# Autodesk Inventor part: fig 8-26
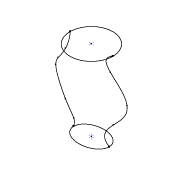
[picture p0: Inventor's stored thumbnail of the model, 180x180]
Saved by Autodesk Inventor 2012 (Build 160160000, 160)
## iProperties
Shininess: 64.0
Length Units: 11269
Angle Units: 11279
Time Units: 11290
Mass Units: 11283
Length Display Precision: 3
Angle Display Precision: 2
Compacted: True
Part Number: fig 8-26
Document SubType Name: Modeling
Created: 2002-12
Designer: deepak
Density: 1 g/cm^3
Material: Default
Density: 0.0
Volumn: 0.0
Area: 0.0
PropertySet Name: Model Information
Control State: 0
Master: False
Checked Out: False
Author: deepak
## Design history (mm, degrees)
sketch "Sketch1"
  geometry: 2 further points; 1 other entity
  constraints: 1 coincident, 3 other
workplane "Work Plane1"
workplane "Work Plane2"
sketch "Sketch3"
  geometry: C1 r 60 at (0, 0); 1 further point
  constraints: 1 centre point, 1 coincident, 1 other
sketch "Sketch4"
  geometry: 8 further points
  constraints: 8 other
sketch "Sketch5"
  geometry: 6 further points
  constraints: 6 other
sketch "Sketch6"
  geometry: 6 further points
  constraints: 6 other
  dimensions: "d20" = 35 distance of point (0, 0) point (-35, 0); "d21" = 0 vertical distance of point (0, 0) point (-35, 0); "d22" = 225 vertical distance of point (0, 0) point (-60, 225); "d23" = 60 horizontal distance of point (0, 0) point (-60, 225); "d24" = 100 horizontal distance of point (0, 0) point (-100, 125); "d25" = 125 vertical distance of point (0, 0) point (-100, 125)
other parameters: "d5" = 125
